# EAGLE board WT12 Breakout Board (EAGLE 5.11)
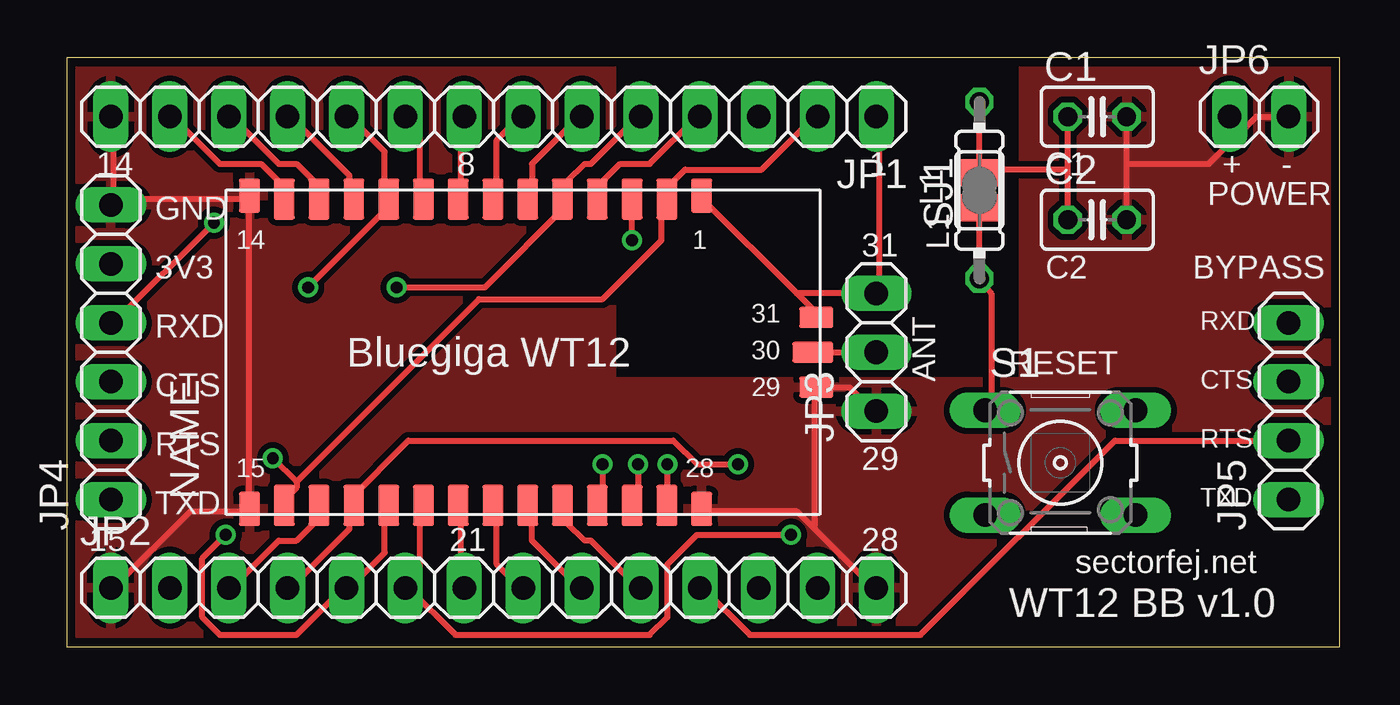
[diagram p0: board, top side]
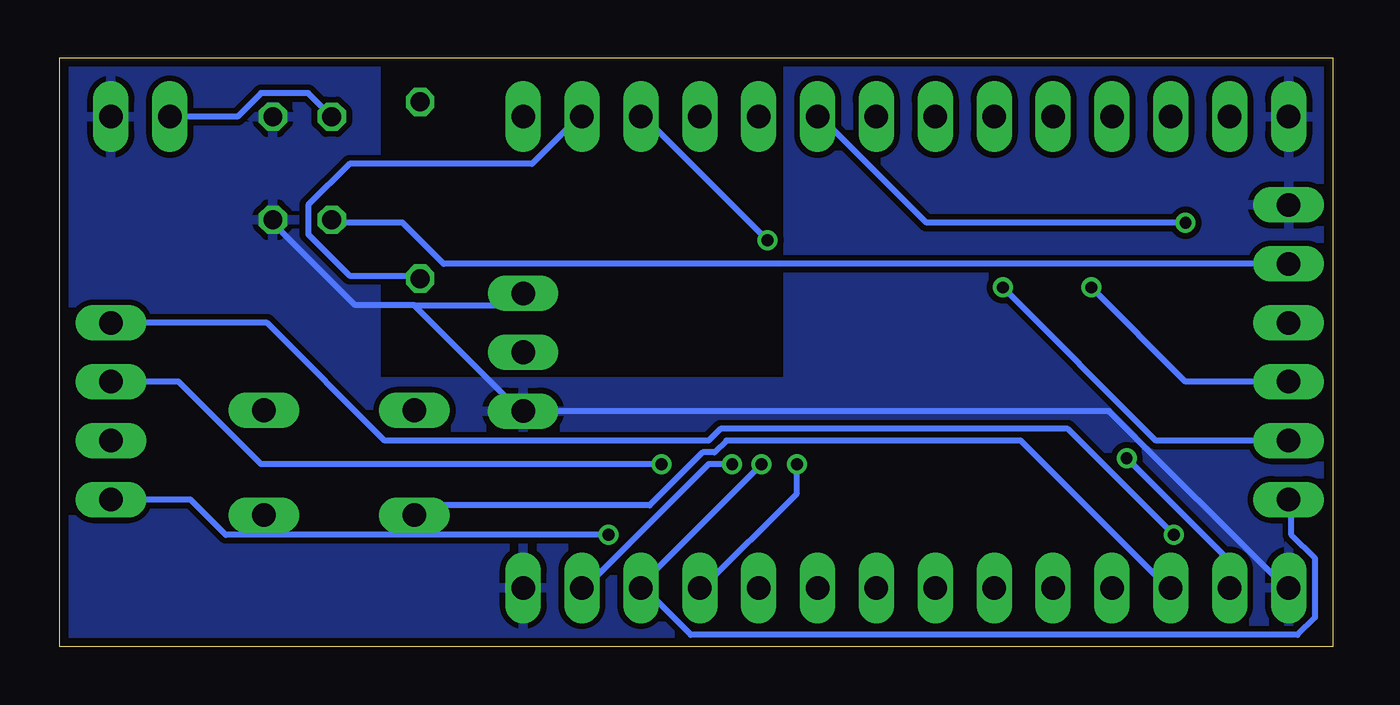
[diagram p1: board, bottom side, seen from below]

Size 54.91 x 25.39 mm. Coordinates in mm from the lower left corner, seen from the top.
Outline: 0,0 54.91,0 54.91,25.39 0,25.39 0,0
Copper layers (1*16): Top 0.0356mm / dielectric 1.5011mm / Bottom 0.0356mm
Design rules "LaenPCBOrder": minimum track width 6mil, minimum drill 13mil, track to track 6mil, track to pad 6mil, pad to pad 6mil, via to via 6mil, smd to smd 6mil, copper to edge 15mil, drill to drill 6mil, minimum pad ring 7mil, minimum via ring 7mil, stop-mask expansion 4mil, vias tented up to drill 0mil, thermal gap 10mil
Net classes: 0 default: width 0.254 mm, drill 0.508 mm, clearance 0.254 mm

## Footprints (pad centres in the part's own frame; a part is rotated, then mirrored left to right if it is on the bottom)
C025-025X050 = drill 0.813 octagon: 1 -1.27,0; 2 1.27,0
1X14 = drill 1.016 long: 1 -16.51,0; 2 -13.97,0; 3 -11.43,0; 4 -8.89,0; 5 -6.35,0; 6 -3.81,0; 7 -1.27,0; 8 1.27,0; 9 3.81,0; 10 6.35,0; 11 8.89,0; 12 11.43,0; 13 13.97,0; 14 16.51,0
1X03 = drill 1.016 long: 1 -2.54,0; 2 0,0; 3 2.54,0
1X06 = drill 1.016 long: 1 -6.35,0; 2 -3.81,0; 3 -1.27,0; 4 1.27,0; 5 3.81,0; 6 6.35,0
1X04 = drill 1.016 long: 1 -3.81,0; 2 -1.27,0; 3 1.27,0; 4 3.81,0
1X02 = drill 1.016 long: 1 -1.27,0; 2 1.27,0
0204/7 = drill 0.813 octagon: 1 -3.81,0; 2 3.81,0
B3F-10XX = drill 1.016 long: 1 -3.251,2.261; 2 3.251,2.261; 3 -3.251,-2.261; 4 3.251,-2.261
SJ = smd 1.168 x 1.6: 1 -0.762,0; 2 0.762,0
WT12 = smd 0.914 x 1.478: GND1 7.7,6.75; GND2 -11.8,6.75; GND3 -11.8,-6.75; GND4 7.7,-6.75 | smd 1.478 x 0.914: GND5 12.65,-1.5; GND6 12.65,1.5 | smd 0.914 x 1.778: MISO 0.2,-6.6; MOSI 1.7,-6.6; NC 6.2,-6.6; NCSB -2.8,-6.6; NCTS -5.8,6.6; NRTS 1.7,6.6; PCMC -8.8,6.6; PCMI -7.3,6.6; PCMO -1.3,6.6; PCMS -10.3,6.6; PIO2 4.7,6.6; PIO3 3.2,6.6; PIO4 -4.3,-6.6; PIO5 3.2,-6.6; PIO6 -7.3,-6.6; PIO7 -5.8,-6.6; RES -8.8,-6.6; RXD 0.2,6.6; SCLK -1.3,-6.6; TXD 4.7,-6.6; USB_D+ -2.8,6.6; USB_D- -4.3,6.6; VDD1 6.2,6.6; VDD2 -10.3,-6.6 | smd 1.778 x 0.914: RF 12.5,0

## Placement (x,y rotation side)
C1  100 nF  [C025-025X050]  44.45,22.86 0 top
C2  NP  [C025-025X050]  44.45,18.41 0 top
JP1  HEADER1  [1X14]  18.41,22.86 180 top
JP2  HEADER2  [1X14]  18.41,2.54 0 top
JP3  ANT  [1X03]  34.92,12.7 90 top
JP4  UART  [1X06]  1.91,12.7 90 top
JP5  BYPASS  [1X04]  52.7,10.16 90 top
JP6  POWER  [1X02]  51.44,22.86 0 top
L1  10 nH  [0204/7]  39.37,19.68 90 top
S1  RESET  [B3F-10XX]  42.86,7.94 0 top
SJ1  PWR  [SJ]  39.37,19.68 90 top
U1  WT12  [WT12]  19.68,12.7 0 top

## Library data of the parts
C1 C2 L1 = resistor
JP1-JP6 = pinhead
S1 = switch-omron; MPN: B3F-1000; OC_FARNELL: 176432; OC_NEWARK: 36M3542
SJ1 = jumper
U1 = wt12

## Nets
3V3: C1.1 C2.1 JP4.5 JP6.1 L1.2 SJ1.2
GND: C1.2 C2.2 JP1.1 JP1.14 JP2.1 JP2.14 JP3.1 JP3.3 JP4.6 JP6.2 U1.GND1 U1.GND2 U1.GND3 U1.GND4 U1.GND5 U1.GND6
MISO: JP2.9 U1.MISO
MOSI: JP2.10 U1.MOSI
NC: JP2.13 U1.NC
NCSB: JP2.7 U1.NCSB
NCTS: JP1.10 JP4.3 U1.NCTS
NRTS: JP1.5 JP4.2 U1.NRTS
PCMC: JP1.12 U1.PCMC
PCMI: JP1.11 U1.PCMI
PCMO: JP1.7 U1.PCMO
PCMS: JP1.13 U1.PCMS
PIO2: JP1.3 U1.PIO2
PIO3: JP1.4 U1.PIO3
PIO4: JP2.6 JP5.1 U1.PIO4
PIO5: JP2.11 JP5.2 U1.PIO5
PIO6: JP2.4 JP5.3 U1.PIO6
PIO7: JP2.5 JP5.4 U1.PIO7
RES: JP2.3 S1.3 U1.RES
RF: JP3.2 U1.RF
RXD: JP1.6 JP4.4 U1.RXD
SCLK: JP2.8 U1.SCLK
TXD: JP2.12 JP4.1 U1.TXD
USB_D+: JP1.8 U1.USB_D+
USB_D-: JP1.9 U1.USB_D-
VCC: JP1.2 JP2.2 L1.1 S1.1 SJ1.1 U1.VDD1 U1.VDD2

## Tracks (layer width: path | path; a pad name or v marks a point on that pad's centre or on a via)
3V3
  Top 0.254: 39.37,20.57 L1.2 | 43.18,20.57 C1.1 | C2.1 43.18,20.57 | 43.18,20.57 39.37,20.57 | 39.37,20.57 SJ1.2
  Bottom 0.254: JP4.5 38.35,16.51 40.13,18.29 43.18,18.29 C2.1 | C1.1 44.2,23.88 46.23,23.88 47.24,22.86 JP6.1
GND
  Top 0.254: JP2.1 2.03,2.54 5.33,5.84 7.87,5.84 U1.GND3 7.87,6.1 7.87,19.3 | 7.87,19.3 2.29,19.3 2.03,19.05 | 2.03,19.05 2.03,22.86 JP1.14 | 2.03,19.05 JP4.6 | 7.87,19.3 U1.GND2 | JP3.1 34.8,10.16 33.78,11.18 32.51,11.18 U1.GND5 32.26,11.18 32.26,5.08 | 32.26,5.08 34.8,2.54 JP2.14 | 32.26,5.08 31.5,5.84 27.43,5.84 U1.GND4 | 45.72,20.83 C1.2 | C2.2 45.72,20.83 | 45.72,20.83 49.28,20.83 51.31,22.86 JP6.2 | 31.5,15.24 32.51,14.22 U1.GND6 | 31.5,15.24 27.43,19.3 U1.GND1 | 31.5,15.24 JP3.3 35.05,15.24 35.05,22.86 JP1.1
  Bottom 0.254: 39.62,14.73 35.56,14.73 35.05,15.24 JP3.3 | 39.62,14.73 42.16,14.73 45.72,18.29 C2.2 | 39.62,14.73 35.05,10.16 JP3.1 9.65,10.16 2.03,2.54 JP2.1
  pour Bottom: 0,25.4 23.5,25.4 23.5,11.43 41.27,11.43 41.27,25.4 54.93,25.4 54.93,0 0,0
  pour Top: 0,25.4 23.5,25.4 23.5,11.43 41.27,11.43 41.27,25.4 54.93,25.4 54.93,0 0,0
MISO
  Top 0.254: U1.MISO 20.07,6.1 20.07,4.57 22.1,2.54 JP2.9
MOSI
  Top 0.254: U1.MOSI 21.59,6.1 21.59,5.33 22.35,4.57 22.61,4.57 24.64,2.54 JP2.10
NC  (via drill 0.51)
  Top 0.254: v25.91,7.87 25.91,6.35 U1.NC
  Bottom 0.254: v25.91,7.87 26.92,7.87 32.26,2.54 JP2.13
NCSB
  Top 0.254: U1.NCSB 17.02,6.1 17.02,2.54 JP2.7
NCTS  (via drill 0.51)
  Top 0.254: JP1.10 12.19,22.86 13.72,21.34 13.72,19.3 U1.NCTS 13.97,19.05 v10.41,15.49
  Bottom 0.254: v10.41,15.49 6.35,11.43 JP4.3
NRTS  (via drill 0.51)
  Top 0.254: JP1.5 24.64,22.86 22.61,20.83 22.35,20.83 21.59,20.07 21.59,19.3 U1.NRTS 21.59,19.05 18.03,15.49 v14.22,15.49
  Bottom 0.254: v14.22,15.49 7.62,8.89 JP4.2
PCMC
  Top 0.254: U1.PCMC 10.67,19.3 10.67,20.07 9.91,20.83 9.14,20.83 7.11,22.86 JP1.12
PCMI
  Top 0.254: U1.PCMI 12.19,19.3 12.19,20.32 9.65,22.86 JP1.11
PCMO
  Top 0.254: U1.PCMO 18.54,19.3 18.54,21.84 19.56,22.86 JP1.7
PCMS
  Top 0.254: U1.PCMS 9.14,19.3 9.14,20.07 8.38,20.83 6.6,20.83 4.57,22.86 JP1.13
PIO2  (via drill 0.51)
  Top 0.254: v24.38,17.53 24.38,19.05 U1.PIO2
  Bottom 0.254: v24.38,17.53 29.72,22.86 JP1.3
PIO3
  Top 0.254: U1.PIO3 23.11,19.3 23.11,20.07 23.88,20.83 25.15,20.83 27.18,22.86 JP1.4
PIO4  (via drill 0.51)
  Top 0.254: 14.73,2.54 15.24,3.05 15.24,6.1 U1.PIO4 | v31.24,4.83 27.18,4.83 25.91,3.56 25.91,1.27 25.15,0.51 16.76,0.51 14.73,2.54 | JP2.6 14.73,2.54
  Bottom 0.254: v31.24,4.83 47.75,4.83 49.28,6.35 JP5.1
PIO5  (via drill 0.51)
  Top 0.254: v23.11,7.87 23.11,6.35 U1.PIO5 | JP5.2 45.21,8.89 36.83,0.51 29.46,0.51 27.43,2.54 JP2.11
  Bottom 0.254: v23.11,7.87 23.11,6.6 27.18,2.54 JP2.11
PIO6  (via drill 0.51)
  Top 0.254: JP2.4 9.65,2.54 12.19,5.08 12.19,6.1 U1.PIO6 12.19,6.35 14.73,8.89 26.16,8.89 27.18,7.87 v28.96,7.87
  Bottom 0.254: v28.96,7.87 46.23,7.87 49.78,11.43 JP5.3
PIO7  (via drill 0.51)
  Top 0.254: U1.PIO7 13.72,6.1 13.72,4.06 12.19,2.54 JP2.5 11.94,2.54 9.91,0.51 6.6,0.51 5.84,1.27 5.84,3.81 v6.86,4.83
  Bottom 0.254: v6.86,4.83 11.43,9.4 26.42,9.4 26.92,8.89 40.89,8.89 45.97,13.97 JP5.4
RES
  Top 0.254: U1.RES 10.67,6.1 10.67,5.33 9.91,4.57 9.14,4.57 7.11,2.54 JP2.3
  Bottom 0.254: S1.3 39.88,6.1 29.46,6.1 27.18,8.38 26.67,8.38 26.16,8.89 13.46,8.89 7.11,2.54 JP2.3
RF
  Top 0.254: U1.RF JP3.2
RXD  (via drill 0.51)
  Top 0.254: U1.RXD 20.07,19.3 20.07,20.83 22.1,22.86 JP1.6 | v6.35,18.29 2.03,13.97 JP4.4
  Bottom 0.254: v6.35,18.29 17.53,18.29 22.1,22.86 JP1.6
SCLK
  Top 0.254: U1.SCLK 18.54,6.1 18.54,3.56 19.56,2.54 JP2.8
TXD  (via drill 0.51)
  Top 0.254: v24.64,7.87 24.64,6.35 U1.TXD
  Bottom 0.254: v24.64,7.87 29.97,2.54 JP2.12 29.72,2.54 27.69,0.51 1.52,0.51 0.76,1.27 0.76,3.81 1.78,4.83 1.78,6.35 JP4.1
USB_D+
  Top 0.254: U1.USB_D+ 17.02,19.3 17.02,22.86 JP1.8
USB_D-
  Top 0.254: U1.USB_D- 15.24,19.3 15.24,22.35 14.73,22.86 JP1.9
VCC  (via drill 0.51)
  Top 0.254: SJ1.1 L1.1 39.37,15.75 39.88,15.24 39.88,10.67 S1.1 | 9.91,7.11 9.91,6.86 9.4,6.35 U1.VDD2 | 9.91,7.11 17.78,14.99 23.11,14.99 25.65,17.53 25.65,19.05 U1.VDD1 25.91,19.3 25.91,19.81 26.67,20.57 29.97,20.57 32.26,22.86 JP1.2 | v8.89,8.13 9.91,7.11
  Bottom 0.254: v8.89,8.13 4.57,3.81 4.57,2.54 JP2.2 | L1.1 39.37,16 42.42,16 44.2,17.78 44.2,19.05 42.42,20.83 34.54,20.83 32.51,22.86 JP1.2

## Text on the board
tPlace: 14 | 8 | 1 | C1 | + | - | L1 | POWER | GND | 14 | 1 | 31 | 3V3 | C2 | BYPASS | 31 | RXD | RXD | Bluegiga WT12 | 30 | RESET | CTS | 29 | ANT | CTS | RTS | RTS | 29 | 15 | 28 | TXD | TXD | 15 | 21 | 28 | sectorfej.net | WT12 BB v1.0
